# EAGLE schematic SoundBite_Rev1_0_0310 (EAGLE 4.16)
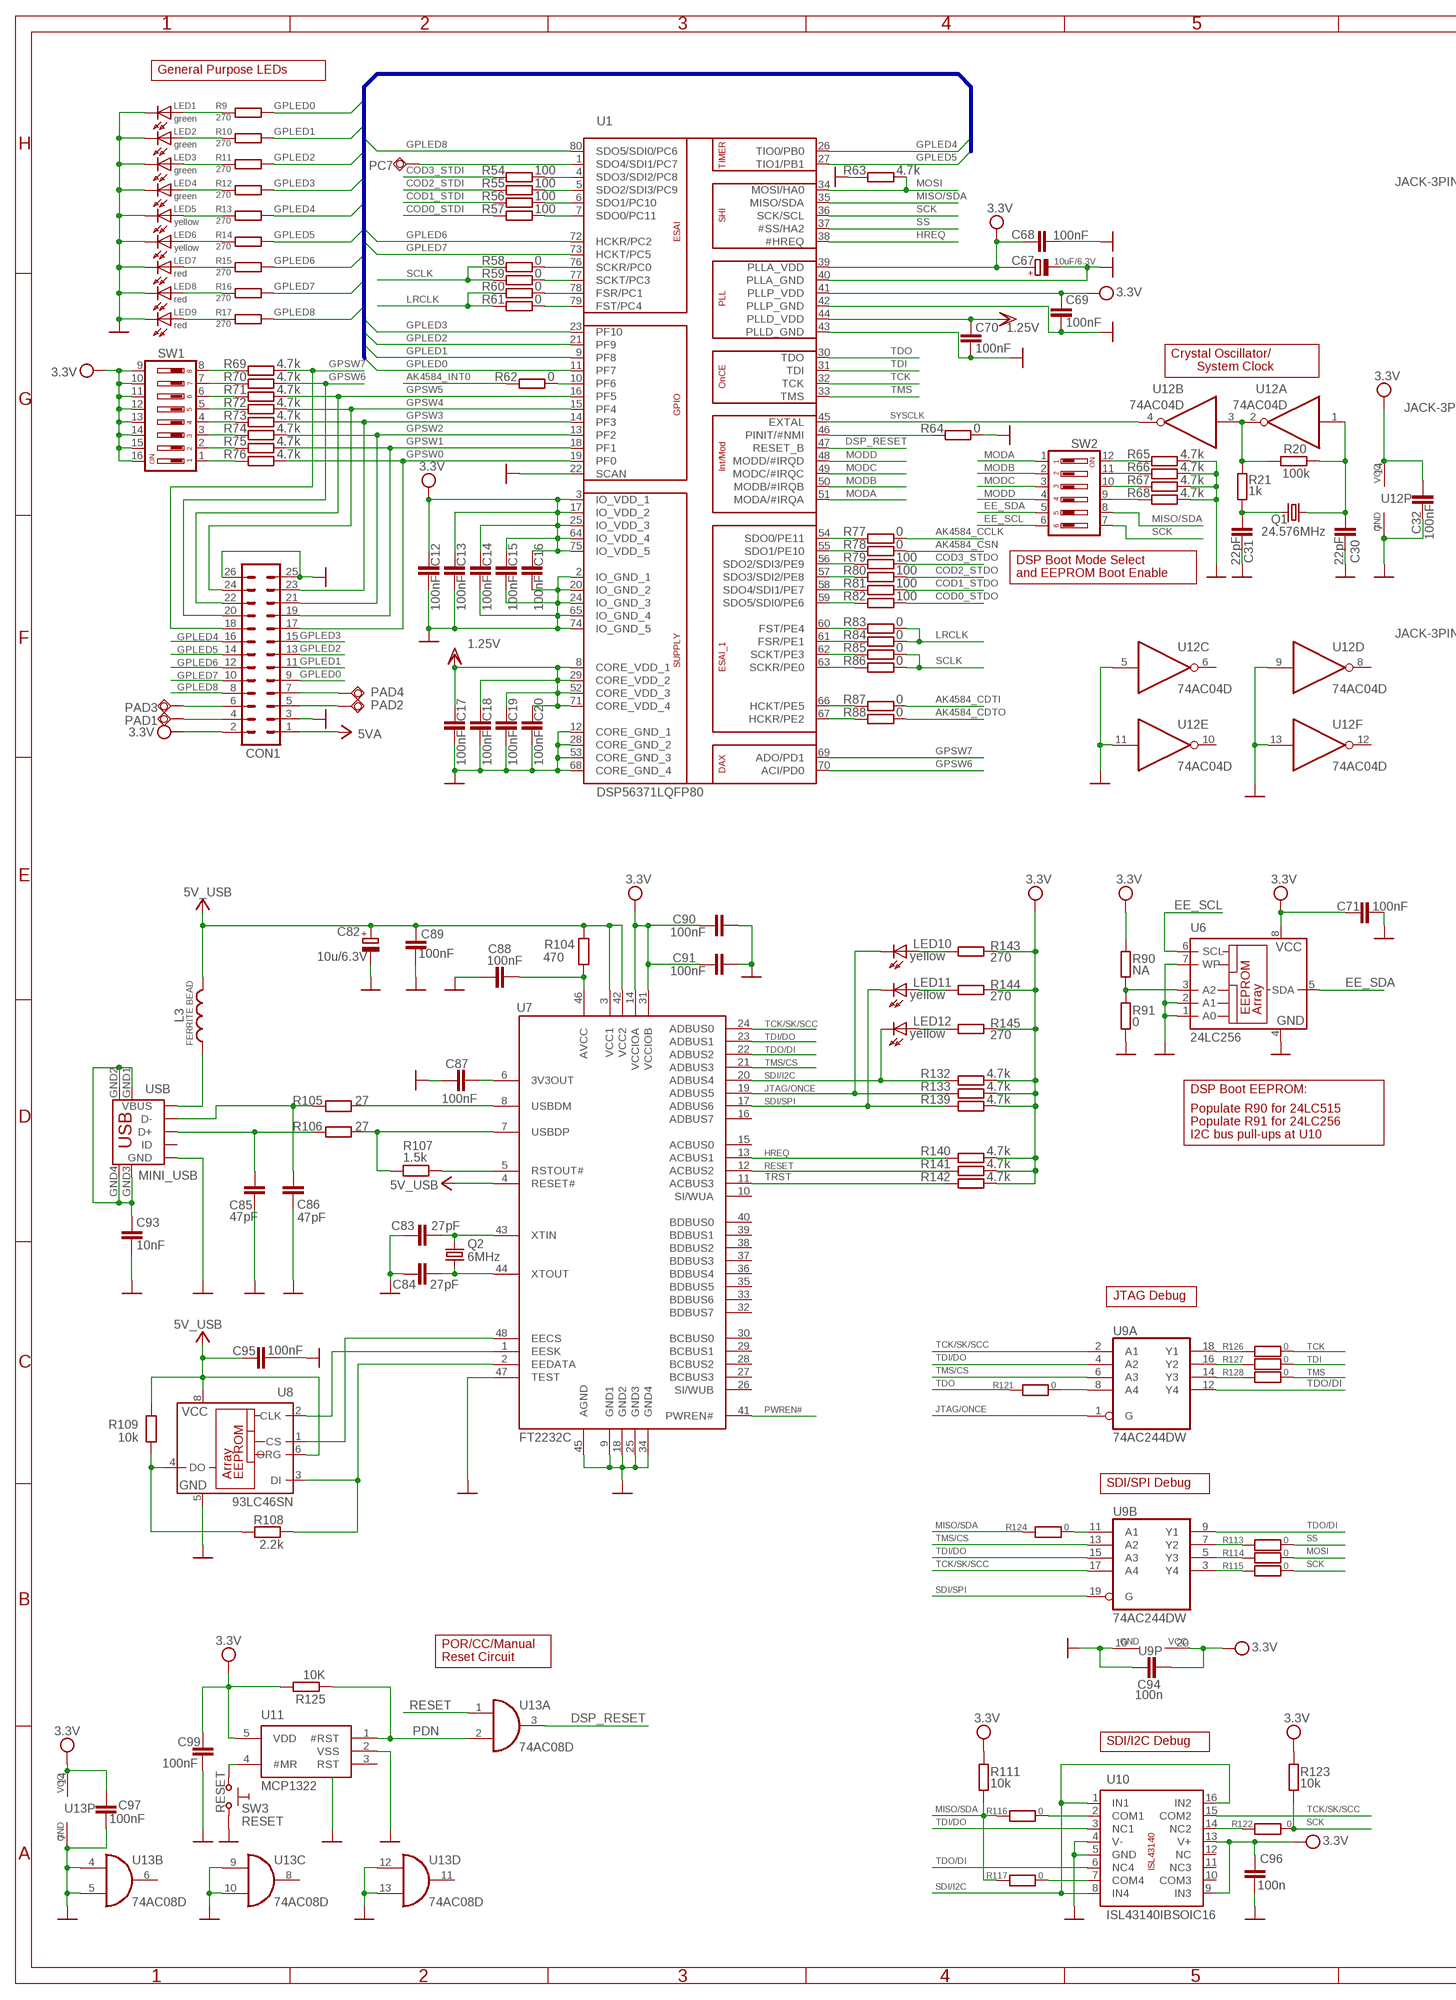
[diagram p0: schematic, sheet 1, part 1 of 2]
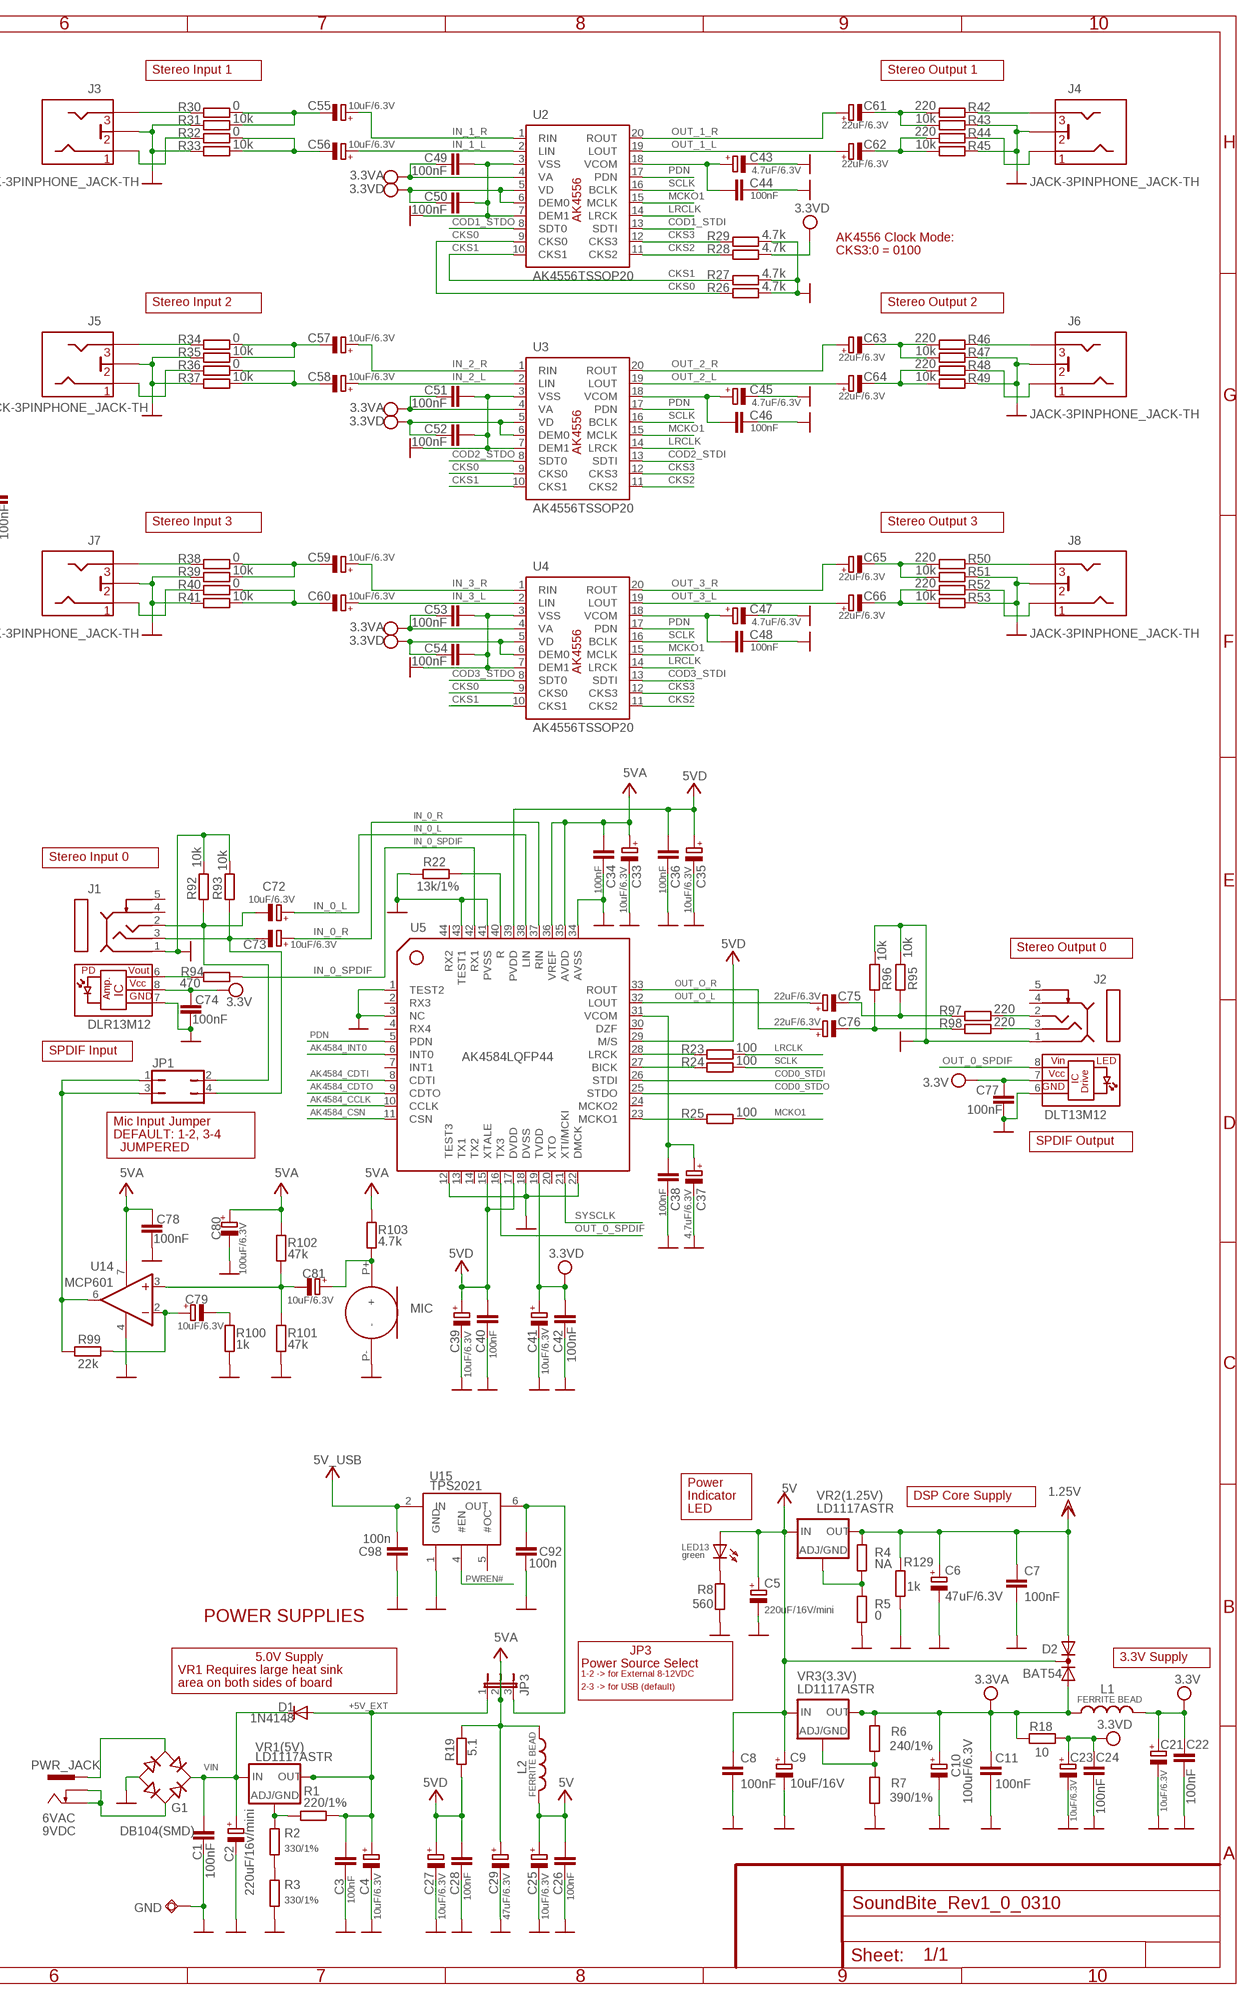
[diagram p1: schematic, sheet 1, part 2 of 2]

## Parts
C1  100nF  C-EUC0805_5MIL  [C0805_5MIL]
C2  220uF/16v/mini  CPOL-EUE3.5-8  [E3,5-8]
C3  100nF  C-EUC0805_5MIL  [C0805_5MIL]
C4  10uF/6.3V  CPOL-EUCT3216  [CT3216]
C5  220uF/16V/mini  CPOL-EUE3.5-8  [E3,5-8]
C6  47uF/6.3V  CPOL-EUCT3528  [CT3528]
C7  100nF  C-EUC0805_5MIL  [C0805_5MIL]
C8  100nF  C-EUC0805_5MIL  [C0805_5MIL]
C9  10uF/16V  CPOL-EUCT3528  [CT3528]
C10  100uF/6.3V  CPOL-EUCT7343  [CT7343]
C11  100nF  C-EUC0805_5MIL  [C0805_5MIL]
C12  100nF  C-EUC0805_5MIL  [C0805_5MIL]
C13  100nF  C-EUC0805_5MIL  [C0805_5MIL]
C14  100nF  C-EUC0805_5MIL  [C0805_5MIL]
C15  100nF  C-EUC0805_5MIL  [C0805_5MIL]
C16  100nF  C-EUC0805_5MIL  [C0805_5MIL]
C17  100nF  C-EUC0805_5MIL  [C0805_5MIL]
C18  100nF  C-EUC0805_5MIL  [C0805_5MIL]
C19  100nF  C-EUC0805_5MIL  [C0805_5MIL]
C20  100nF  C-EUC0805_5MIL  [C0805_5MIL]
C21  10uF/6.3V  CPOL-EUCT3216  [CT3216]
C22  100nF  C-EUC0805_5MIL  [C0805_5MIL]
C23  10uF/6.3V  CPOL-EUCT3216  [CT3216]
C24  100nF  C-EUC0805_5MIL  [C0805_5MIL]
C25  10uF/6.3V  CPOL-EUCT3216  [CT3216]
C26  100nF  C-EUC0805_5MIL  [C0805_5MIL]
C27  10uF/6.3V  CPOL-EUCT3216  [CT3216]
C28  100nF  C-EUC0805_5MIL  [C0805_5MIL]
C29  47uF/6.3V  CPOL-EUCT3528  [CT3528]
C30  22pF  C-EUC0805_5MIL  [C0805_5MIL]
C31  22pF  C-EUC0805_5MIL  [C0805_5MIL]
C32  100nF  C-EUC0805_5MIL  [C0805_5MIL]
C33  10uF/6.3V  CPOL-EUCT3216  [CT3216]
C34  100nF  C-EUC0805_5MIL  [C0805_5MIL]
C35  10uF/6.3V  CPOL-EUCT3216  [CT3216]
C36  100nF  C-EUC0805_5MIL  [C0805_5MIL]
C37  4.7uF/6.3V  CPOL-EUCT3216  [CT3216]
C38  100nF  C-EUC0805_5MIL  [C0805_5MIL]
C39  10uF/6.3V  CPOL-EUCT3216  [CT3216]
C40  100nF  C-EUC0805_5MIL  [C0805_5MIL]
C41  10uF/6.3V  CPOL-EUCT3216  [CT3216]
C42  100nF  C-EUC0805_5MIL  [C0805_5MIL]
C43  4.7uF/6.3V  CPOL-EUCT3216  [CT3216]
C44  100nF  C-EUC0805_5MIL  [C0805_5MIL]
C45  4.7uF/6.3V  CPOL-EUCT3216  [CT3216]
C46  100nF  C-EUC0805_5MIL  [C0805_5MIL]
C47  4.7uF/6.3V  CPOL-EUCT3216  [CT3216]
C48  100nF  C-EUC0805_5MIL  [C0805_5MIL]
C49  100nF  C-EUC0805_5MIL  [C0805_5MIL]
C50  100nF  C-EUC0805_5MIL  [C0805_5MIL]
C51  100nF  C-EUC0805_5MIL  [C0805_5MIL]
C52  100nF  C-EUC0805_5MIL  [C0805_5MIL]
C53  100nF  C-EUC0805_5MIL  [C0805_5MIL]
C54  100nF  C-EUC0805_5MIL  [C0805_5MIL]
C55  10uF/6.3V  CPOL-EUCT3216  [CT3216]
C56  10uF/6.3V  CPOL-EUCT3216  [CT3216]
C57  10uF/6.3V  CPOL-EUCT3216  [CT3216]
C58  10uF/6.3V  CPOL-EUCT3216  [CT3216]
C59  10uF/6.3V  CPOL-EUCT3216  [CT3216]
C60  10uF/6.3V  CPOL-EUCT3216  [CT3216]
C61  22uF/6.3V  CPOL-EUCT3216  [CT3216]
C62  22uF/6.3V  CPOL-EUCT3216  [CT3216]
C63  22uF/6.3V  CPOL-EUCT3216  [CT3216]
C64  22uF/6.3V  CPOL-EUCT3216  [CT3216]
C65  22uF/6.3V  CPOL-EUCT3216  [CT3216]
C66  22uF/6.3V  CPOL-EUCT3216  [CT3216]
C67  10uF/6.3V  CPOL-EUCT3216  [CT3216]
C68  100nF  C-EUC0805_5MIL  [C0805_5MIL]
C69  100nF  C-EUC0805_5MIL  [C0805_5MIL]
C70  100nF  C-EUC0805_5MIL  [C0805_5MIL]
C71  100nF  C-EUC0805_5MIL  [C0805_5MIL]
C72  10uF/6.3V  CPOL-EUCT3216  [CT3216]
C73  10uF/6.3V  CPOL-EUCT3216  [CT3216]
C74  100nF  C-EUC0805_5MIL  [C0805_5MIL]
C75  22uF/6.3V  CPOL-EUCT3216  [CT3216]
C76  22uF/6.3V  CPOL-EUCT3216  [CT3216]
C77  100nF  C-EUC0805_5MIL  [C0805_5MIL]
C78  100nF  C-EUC0805_5MIL  [C0805_5MIL]
C79  10uF/6.3V  CPOL-EUCT3216  [CT3216]
C80  100uF/6.3V  CPOL-EUCT7343  [CT7343]
C81  10uF/6.3V  CPOL-EUCT3216  [CT3216]
C82  10u/6.3V  CPOL-EUCT3216  [CT3216]
C83  27pF  C_0805  [0805]
C84  27pF  C_0805  [0805]
C85  47pF  C_0805  [0805]
C86  47pF  C_0805  [0805]
C87  100nF  C_0805  [0805]
C88  100nF  C_0805  [0805]
C89  100nF  C_0805  [0805]
C90  100nF  C_0805  [0805]
C91  100nF  C_0805  [0805]
C92  100n  C_0805  [0805]
C93  10nF  C-EUC0805_5MIL  [C0805_5MIL]
C94  100n  C_0805  [0805]
C95  100nF  C_0805  [0805]
C96  100n  C_0805  [0805]
C97  100nF  C-EUC0805_5MIL  [C0805_5MIL]
C98  100n  C_0805  [0805]
C99  100nF  C-EUC0805_5MIL  [C0805_5MIL]
CON1  ML26  [ML26]
D1  1N4148  D-SOD-80  [SOD80]
D2  BAT54  DIODE_AC-CA_  [SOT23C]
G1  DB104(SMD)  B-DIL3  [DB104_SMD]
GND  TESTPAD3  [TEST_PAD40/70/SQUARE]
J1  DLR13M12  [GP1FD210RP]
J2  DLT13M12  [GP1FD210RP]
J3  JACK-3PINPHONE_JACK-TH  [PHONE_JACK-TH]
J4  JACK-3PINPHONE_JACK-TH  [PHONE_JACK-TH]
J5  JACK-3PINPHONE_JACK-TH  [PHONE_JACK-TH]
J6  JACK-3PINPHONE_JACK-TH  [PHONE_JACK-TH]
J7  JACK-3PINPHONE_JACK-TH  [PHONE_JACK-TH]
J8  JACK-3PINPHONE_JACK-TH  [PHONE_JACK-TH]
JP1  JP2Q  [JP2Q]
JP3  JP2E  [JP2]
L1  FERRITE BEAD  L-USL0805  [L0805]
L2  FERRITE BEAD  L-USL0805  [L0805]
L3  FERRITE BEAD  L-USL0805  [L0805]
LED1  green  LED_SML-010  [SML-010]
LED2  green  LED_SML-010  [SML-010]
LED3  green  LED_SML-010  [SML-010]
LED4  green  LED_SML-010  [SML-010]
LED5  yellow  LED_SML-010  [SML-010]
LED6  yellow  LED_SML-010  [SML-010]
LED7  red  LED_SML-010  [SML-010]
LED8  red  LED_SML-010  [SML-010]
LED9  red  LED_SML-010  [SML-010]
LED10  yellow  LED_SML-010  [SML-010]
LED11  yellow  LED_SML-010  [SML-010]
LED12  yellow  LED_SML-010  [SML-010]
LED13  green  LED_SML-010  [SML-010]
MIC  MICR  [MIC]
PAD1  TESTPAD80/50  [SMD80/50]
PAD2  TESTPAD80/50  [SMD80/50]
PAD3  TESTPAD80/50  [SMD80/50]
PAD4  TESTPAD80/50  [SMD80/50]
PC7  TESTPAD80/50  [SMD80/50]
PWR_JACK  PWR-JAK3  [PWR_JACK_UNI]
Q1  24.576MHz  HC49/S  [HC49/S]
Q2  6MHz  CRYTALHC49S  [HC49/S@2]
R1  220/1%  R-EU_R0805_5MIL  [R0805_5MIL]
R2  330/1%  R-EU_R0805_5MIL  [R0805_5MIL]
R3  330/1%  R-EU_R0805_5MIL  [R0805_5MIL]
R4  NA  R-EU_R0805_5MIL  [R0805_5MIL]
R5  0  R-EU_R0805_5MIL  [R0805_5MIL]
R6  240/1%  R-EU_R0805_5MIL  [R0805_5MIL]
R7  390/1%  R-EU_R0805_5MIL  [R0805_5MIL]
R8  560  R-EU_R0805_5MIL  [R0805_5MIL]
R9  270  R-EU_R0805_5MIL  [R0805_5MIL]
R10  270  R-EU_R0805_5MIL  [R0805_5MIL]
R11  270  R-EU_R0805_5MIL  [R0805_5MIL]
R12  270  R-EU_R0805_5MIL  [R0805_5MIL]
R13  270  R-EU_R0805_5MIL  [R0805_5MIL]
R14  270  R-EU_R0805_5MIL  [R0805_5MIL]
R15  270  R-EU_R0805_5MIL  [R0805_5MIL]
R16  270  R-EU_R0805_5MIL  [R0805_5MIL]
R17  270  R-EU_R0805_5MIL  [R0805_5MIL]
R18  10  R-EU_R0805_5MIL  [R0805_5MIL]
R19  5.1  R-EU_R0805_5MIL  [R0805_5MIL]
R20  100k  R-EU_R0805_5MIL  [R0805_5MIL]
R21  1k  R-EU_R0805_5MIL  [R0805_5MIL]
R22  13k/1%  R-EU_R0805_5MIL  [R0805_5MIL]
R23  100  R-EU_R0805_5MIL  [R0805_5MIL]
R24  100  R-EU_R0805_5MIL  [R0805_5MIL]
R25  100  R-EU_R0805_5MIL  [R0805_5MIL]
R26  4.7k  R-EU_R0805_5MIL  [R0805_5MIL]
R27  4.7k  R-EU_R0805_5MIL  [R0805_5MIL]
R28  4.7k  R-EU_R0805_5MIL  [R0805_5MIL]
R29  4.7k  R-EU_R0805_5MIL  [R0805_5MIL]
R30  0  R-EU_R0805_5MIL  [R0805_5MIL]
R31  10k  R-EU_R0805_5MIL  [R0805_5MIL]
R32  0  R-EU_R0805_5MIL  [R0805_5MIL]
R33  10k  R-EU_R0805_5MIL  [R0805_5MIL]
R34  0  R-EU_R0805_5MIL  [R0805_5MIL]
R35  10k  R-EU_R0805_5MIL  [R0805_5MIL]
R36  0  R-EU_R0805_5MIL  [R0805_5MIL]
R37  10k  R-EU_R0805_5MIL  [R0805_5MIL]
R38  0  R-EU_R0805_5MIL  [R0805_5MIL]
R39  10k  R-EU_R0805_5MIL  [R0805_5MIL]
R40  0  R-EU_R0805_5MIL  [R0805_5MIL]
R41  10k  R-EU_R0805_5MIL  [R0805_5MIL]
R42  220  R-EU_R0805_5MIL  [R0805_5MIL]
R43  10k  R-EU_R0805_5MIL  [R0805_5MIL]
R44  220  R-EU_R0805_5MIL  [R0805_5MIL]
R45  10k  R-EU_R0805_5MIL  [R0805_5MIL]
R46  220  R-EU_R0805_5MIL  [R0805_5MIL]
R47  10k  R-EU_R0805_5MIL  [R0805_5MIL]
R48  220  R-EU_R0805_5MIL  [R0805_5MIL]
R49  10k  R-EU_R0805_5MIL  [R0805_5MIL]
R50  220  R-EU_R0805_5MIL  [R0805_5MIL]
R51  10k  R-EU_R0805_5MIL  [R0805_5MIL]
R52  220  R-EU_R0805_5MIL  [R0805_5MIL]
R53  10k  R-EU_R0805_5MIL  [R0805_5MIL]
R54  100  R-EU_R0805_5MIL  [R0805_5MIL]
R55  100  R-EU_R0805_5MIL  [R0805_5MIL]
R56  100  R-EU_R0805_5MIL  [R0805_5MIL]
R57  100  R-EU_R0805_5MIL  [R0805_5MIL]
R58  0  R-EU_R0805_5MIL  [R0805_5MIL]
R59  0  R-EU_R0805_5MIL  [R0805_5MIL]
R60  0  R-EU_R0805_5MIL  [R0805_5MIL]
R61  0  R-EU_R0805_5MIL  [R0805_5MIL]
R62  0  R-EU_R0805_5MIL  [R0805_5MIL]
R63  4.7k  R-EU_R0805_5MIL  [R0805_5MIL]
R64  0  R-EU_R0805_5MIL  [R0805_5MIL]
R65  4.7k  R-EU_R0805_5MIL  [R0805_5MIL]
R66  4.7k  R-EU_R0805_5MIL  [R0805_5MIL]
R67  4.7k  R-EU_R0805_5MIL  [R0805_5MIL]
R68  4.7k  R-EU_R0805_5MIL  [R0805_5MIL]
R69  4.7k  R-EU_R0805_5MIL  [R0805_5MIL]
R70  4.7k  R-EU_R0805_5MIL  [R0805_5MIL]
R71  4.7k  R-EU_R0805_5MIL  [R0805_5MIL]
R72  4.7k  R-EU_R0805_5MIL  [R0805_5MIL]
R73  4.7k  R-EU_R0805_5MIL  [R0805_5MIL]
R74  4.7k  R-EU_R0805_5MIL  [R0805_5MIL]
R75  4.7k  R-EU_R0805_5MIL  [R0805_5MIL]
R76  4.7k  R-EU_R0805_5MIL  [R0805_5MIL]
R77  0  R-EU_R0805_5MIL  [R0805_5MIL]
R78  0  R-EU_R0805_5MIL  [R0805_5MIL]
R79  100  R-EU_R0805_5MIL  [R0805_5MIL]
R80  100  R-EU_R0805_5MIL  [R0805_5MIL]
R81  100  R-EU_R0805_5MIL  [R0805_5MIL]
R82  100  R-EU_R0805_5MIL  [R0805_5MIL]
R83  0  R-EU_R0805_5MIL  [R0805_5MIL]
R84  0  R-EU_R0805_5MIL  [R0805_5MIL]
R85  0  R-EU_R0805_5MIL  [R0805_5MIL]
R86  0  R-EU_R0805_5MIL  [R0805_5MIL]
R87  0  R-EU_R0805_5MIL  [R0805_5MIL]
R88  0  R-EU_R0805_5MIL  [R0805_5MIL]
R90  NA  R-EU_R0805_5MIL  [R0805_5MIL]
R91  0  R-EU_R0805_5MIL  [R0805_5MIL]
R92  10k  R-EU_R0805_5MIL  [R0805_5MIL]
R93  10k  R-EU_R0805_5MIL  [R0805_5MIL]
R94  470  R-EU_R0805_5MIL  [R0805_5MIL]
R95  10k  R-EU_R0805_5MIL  [R0805_5MIL]
R96  10k  R-EU_R0805_5MIL  [R0805_5MIL]
R97  220  R-EU_R0805_5MIL  [R0805_5MIL]
R98  220  R-EU_R0805_5MIL  [R0805_5MIL]
R99  22k  R-EU_R0805_5MIL  [R0805_5MIL]
R100  1k  R-EU_R0805_5MIL  [R0805_5MIL]
R101  47k  R-EU_R0805_5MIL  [R0805_5MIL]
R102  47k  R-EU_R0805_5MIL  [R0805_5MIL]
R103  4.7k  R-EU_R0805_5MIL  [R0805_5MIL]
R104  470  R_0805  [0805]
R105  27  R_0805  [0805]
R106  27  R_0805  [0805]
R107  1.5k  R_0805  [0805]
R108  2.2k  R_0805  [0805]
R109  10k  R_0805  [0805]
R111  10k  R-EU_R0805_5MIL  [R0805_5MIL]
R113  0  R_0805  [0805]
R114  0  R_0805  [0805]
R115  0  R_0805  [0805]
R116  0  R_0805  [0805]
R117  0  R_0805  [0805]
R121  0  R_0805  [0805]
R122  0  R_0805  [0805]
R123  10k  R-EU_R0805_5MIL  [R0805_5MIL]
R124  0  R_0805  [0805]
R125  10K  R-EU_R0805_5MIL  [R0805_5MIL]
R126  0  R_0805  [0805]
R127  0  R_0805  [0805]
R128  0  R_0805  [0805]
R129  1k  R-EU_R0805_5MIL  [R0805_5MIL]
R132  4.7k  R-EU_R0805_5MIL  [R0805_5MIL]
R133  4.7k  R-EU_R0805_5MIL  [R0805_5MIL]
R139  4.7k  R-EU_R0805_5MIL  [R0805_5MIL]
R140  4.7k  R-EU_R0805_5MIL  [R0805_5MIL]
R141  4.7k  R-EU_R0805_5MIL  [R0805_5MIL]
R142  4.7k  R-EU_R0805_5MIL  [R0805_5MIL]
R143  270  R-EU_R0805_5MIL  [R0805_5MIL]
R144  270  R-EU_R0805_5MIL  [R0805_5MIL]
R145  270  R-EU_R0805_5MIL  [R0805_5MIL]
SW1  DIP08YL  [DIP08YL]
SW2  DIP06YL  [DIP06YL]
SW3  RESET  SW-TAKT6  [SW-TAKT_6X3.5_SMD]
U1  DSP56371LQFP80  [LQFP80]
U2  AK4556TSSOP20  [TSSOP20]
U3  AK4556TSSOP20  [TSSOP20]
U4  AK4556TSSOP20  [TSSOP20]
U5  AK4584LQFP44  [LQFP44]
U6  24LC256  24LCXX  [SO-08MN]
U7  FT2232C  [FT2232C_LQFP48]
U8  93LC46SN  [SO-08]
U9  74AC244DW  [SO20W]
U10  ISL43140IBSOIC16  [SOIC16]
U11  MCP1322  [SOT23-5]
U12  74AC04D  [SO14]
U13  74AC08D  [SO14]
U14  MCP601  LM307D  [SO08]
U15  TPS2021  TPS2020G8  [R-PDSO-G8]
USB  MINI_USB  MINI_USB9  [USB_MINI_9PIN]
VR1(5V)  LD1117ASTR  LM1117  [SOT223]
VR2(1.25V)  LD1117ASTR  LM1117  [SOT223]
VR3(3.3V)  LD1117ASTR  LM1117  [SOT223]

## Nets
+5V: C5.+ C8.1 C9.+ C25.+ C26.1 D2.3(K) L2.2 LED13.A VR2(1.25V).3(IN) VR3(3.3V).3(IN) ; supply symbol labelled 5V
+5V_EXT: C3.1 C4.+ D1.2(A) JP3.1 R1.2 VR1(5V).2(OUT) VR1(5V).4(RAD)
AK4584_CCLK: R77.2 U5.10(CCLK)
AK4584_CDTI: R87.2 U5.8(CDTI)
AK4584_CDTO: R88.2 U5.9(CDTO)
AK4584_CSN: R78.2 U5.11(CSN)
AK4584_INT0: R62.1 U5.6(INT0)
CKS0: R26.1 U2.9(CKS0) U3.9(CKS0) U4.9(CKS0)
CKS1: R27.1 U2.10(CKS1) U3.10(CKS1) U4.10(CKS1)
CKS2: R28.1 U2.11(CKS2) U3.11(CKS2) U4.11(CKS2)
CKS3: R29.1 U2.12(CKS3) U3.12(CKS3) U4.12(CKS3)
COD0_STDI: R57.1 U5.26(STDI)
COD0_STDO: R82.2 U5.25(STDO)
COD1_STDI: R56.1 U2.13(SDTI)
COD1_STDO: R81.2 U2.8(SDT0)
COD2_STDI: R55.1 U3.13(SDTI)
COD2_STDO: R80.2 U3.8(SDT0)
COD3_STDI: R54.1 U4.13(SDTI)
COD3_STDO: R79.2 U4.8(SDT0)
DSP_RESET: U1.47(RESET_B) U13.3(A:O)
EE_SCL: SW2.6 U6.6(SCL)
EE_SDA: SW2.5 U6.5(SDA)
GND: C1.2 C2.- C3.2 C4.- C5.- C6.- C7.2 C8.2 C9.- C10.- C11.2 C12.2 C13.2 C14.2 C15.2 C16.2 C17.2 C18.2 C19.2 C20.2 C21.- C22.2 C23.- C24.2 C25.- C26.2 C27.- C28.2 C29.- C30.2 C31.2 C32.2 C33.- C34.2 C35.- C36.2 C37.- C38.2 C39.- C40.2 C41.- C42.2 C43.- C44.2 C45.- C46.2 C47.- C48.2 C49.2 C50.2 C51.2 C52.2 C53.2 C54.2 C67.- C68.2 C69.2 C70.2 C71.2 C74.2 C77.2 C78.2 C80.- C82.- C83.P$2 C84.P$2 C85.P$2 C86.P$2 C87.P$2 C88.P$2 C89.P$2 C90.P$1 C91.P$1 C92.P$1 C93.1 C94.P$2 C95.P$1 C96.P$2 C97.2 C98.P$1 C99.2 CON1.3 CON1.25 CON1.26 G1.- GND.P$1(PP) J1.1 J1.7 J2.1 J2.6 J3.2 J4.2 J5.2 J6.2 J7.2 J8.2 LED1.C LED2.C LED3.C LED4.C LED5.C LED6.C LED7.C LED8.C LED9.C MIC.P-(-) R3.1 R5.1 R7.1 R8.1 R22.1 R26.2 R27.2 R29.2 R31.1 R33.1 R35.1 R37.1 R39.1 R41.1 R43.1 R45.1 R47.1 R49.1 R51.1 R53.1 R63.1 R64.2 R65.2 R66.2 R67.2 R68.2 R91.1 R92.2 R93.2 R95.2 R96.2 R100.2 R101.2 R129.1 SW3.P$2 U1.2(IO_GND_1) U1.12(CORE_GND_1) U1.20(IO_GND_2) U1.22(SCAN) U1.24(IO_GND_3) U1.28(CORE_GND_2) U1.40(PLLA_GND) U1.42(PLLP_GND) U1.43(PLLD_GND) U1.53(CORE_GND_3) U1.65(IO_GND_4) U1.68(CORE_GND_4) U1.74(IO_GND_5) U2.3(VSS) U2.7(DEM1) U3.3(VSS) U3.7(DEM1) U4.3(VSS) U4.7(DEM1) U5.1(TEST2) U5.3(NC) U5.12(TEST3) U5.18(DVSS) U5.22(DMCK) U5.34(AVSS) U5.41(PVSS) U5.43(TEST1) U6.1(A0) U6.2(A1) U6.4(GND) U6.7(WP) U7.9(GND1) U7.18(GND2) U7.25(GND3) U7.34(GND4) U7.45(AGND) U7.47(TEST) U8.5(GND) U9.10(P:GND) U10.4(V-) U10.5(GND) U11.2(VSS) U12.5(C:I) U12.7(P:GND) U12.9(D:I) U12.11(E:I) U12.13(F:I) U13.4(B:I0) U13.5(B:I1) U13.7(P:GND) U13.9(C:I0) U13.10(C:I1) U13.12(D:I0) U13.13(D:I1) U14.4(V-) U15.1(GND) USB.GND
GPLED0: CON1.9 R9.2 U1.11(PF7)
GPLED1: CON1.11 R10.2 U1.9(PF8)
GPLED2: CON1.13 R11.2 U1.21(PF9)
GPLED3: CON1.15 R12.2 U1.23(PF10)
GPLED4: CON1.16 R13.2 U1.26(TIO0/PB0)
GPLED5: CON1.14 R14.2 U1.27(TIO1/PB1)
GPLED6: CON1.12 R15.2 U1.72(HCKR/PC2)
GPLED7: CON1.10 R16.2 U1.73(HCKT/PC5)
GPLED8: CON1.8 R17.2 U1.80(SDO5/SDI0/PC6)
GPSW0: CON1.17 R76.2 U1.19(PF0)
GPSW1: CON1.19 R75.2 U1.18(PF1)
GPSW2: CON1.21 R74.2 U1.13(PF2)
GPSW3: CON1.23 R73.2 U1.14(PF3)
GPSW4: CON1.24 R72.2 U1.15(PF4)
GPSW5: CON1.22 R71.2 U1.16(PF5)
GPSW6: CON1.20 R70.2 U1.70(ACI/PD0)
GPSW7: CON1.18 R69.2 U1.69(ADO/PD1)
HREQ: R140.1 U1.38(#HREQ) U7.13(ACBUS1)
IN_0_L: C72.+ U5.38(LIN)
IN_0_R: C73.+ U5.37(RIN)
IN_0_SPDIF: R94.1 U5.42(RX1)
IN_1_L: C56.+ U2.2(LIN)
IN_1_R: C55.+ U2.1(RIN)
IN_2_L: C58.+ U3.2(LIN)
IN_2_R: C57.+ U3.1(RIN)
IN_3_L: C60.+ U4.2(LIN)
IN_3_R: C59.+ U4.1(RIN)
JTAG/ONCE: LED10.C R133.1 U7.19(ADBUS5) U9.1(A:G)
LRCLK: R23.2 R60.1 R61.1 R83.2 R84.2 U2.14(LRCK) U3.14(LRCK) U4.14(LRCK)
MCKO1: R25.2 U2.15(MCLK) U3.15(MCLK) U4.15(MCLK)
MISO/SDA: R111.2 R116.P$2 R117.P$2 R124.P$2 SW2.8 U1.35(MISO/SDA)
MODA: SW2.1 U1.51(MODA/#IRQA)
MODB: SW2.2 U1.50(MODB/#IRQB)
MODC: SW2.3 U1.49(MODC/#IRQC)
MODD: SW2.4 U1.48(MODD/#IRQD)
MOSI: R63.2 R114.P$1 U1.34(MOSI/HA0)
N$1: R22.2 U5.40(R)
N$2: C30.1 Q1.1 R20.1 U12.1(A:I)
N$3: C31.1 Q1.2 R21.1
N$4: R20.2 R21.2 U12.2(A:O) U12.3(B:I)
N$5: C37.+ C38.1 U5.31(VCOM)
N$6: R23.1 U5.28(LRCK)
N$7: R24.1 U5.27(BICK)
N$8: C43.+ C44.1 U2.18(VCOM)
N$9: C45.+ C46.1 U3.18(VCOM)
N$10: C47.+ C48.1 U4.18(VCOM)
N$11: C55.- R30.2 R31.2
N$12: R25.1 U5.23(MCKO1)
N$13: J8.3 R50.1
N$14: R58.2 U1.76(SCKR/PC0)
N$15: LED13.C R8.2
N$16: C56.- R32.2 R33.2
N$17: J3.1 R32.1
N$18: C57.- R34.2 R35.2
N$19: J5.3 R34.1
N$20: C58.- R36.2 R37.2
N$21: J5.1 R36.1
N$22: R59.2 U1.77(SCKT/PC3)
N$23: C59.- R38.2 R39.2
N$24: J7.3 R38.1
N$25: C60.- R40.2 R41.2
N$26: J7.1 R40.1
N$27: R60.2 U1.78(FSR/PC1)
N$28: LED1.A R9.1
N$29: C61.- R42.2 R43.2
N$30: J4.3 R42.1
N$31: C62.- R44.2 R45.2
N$32: J4.1 R44.1
N$33: LED2.A R10.1
N$34: C63.- R46.2 R47.2
N$35: LED3.A R11.1
N$36: R2.1 R3.2
N$37: J6.3 R46.1
N$38: R6.1 R7.2 VR3(3.3V).1(ADJ/GND)
N$39: C64.- R48.2 R49.2
N$40: J6.1 R48.1
N$41: C65.- R50.2 R51.2
N$43: C66.- R52.2 R53.2
N$44: J8.1 R52.1
N$45: R54.2 U1.4(SDO3/SDI2/PC8)
N$46: R55.2 U1.5(SDO2/SDI3/PC9)
N$47: R56.2 U1.6(SDO1/PC10)
N$48: R57.2 U1.7(SDO0/PC11)
N$49: R61.2 U1.79(FST/PC4)
N$50: R62.2 U1.10(PF6)
N$51: R65.1 SW2.12
N$52: R64.1 U1.46(PINIT/#NMI)
N$53: R66.1 SW2.11
N$54: R67.1 SW2.10
N$55: R68.1 SW2.9
N$56: R4.1 R5.2 VR2(1.25V).1(ADJ/GND)
N$57: R69.1 SW1.8
N$58: R70.1 SW1.7
N$59: R71.1 SW1.6
N$60: R72.1 SW1.5
N$61: R73.1 SW1.4
N$62: R74.1 SW1.3
N$63: R75.1 SW1.2
N$64: R76.1 SW1.1
N$65: R77.1 U1.54(SDO0/PE11)
N$66: R78.1 U1.55(SDO1/PE10)
N$67: R79.1 U1.56(SDO2/SDI3/PE9)
N$68: R80.1 U1.57(SDO3/SDI2/PE8)
N$69: R81.1 U1.58(SDO4/SDI1/PE7)
N$70: R82.1 U1.59(SDO5/SDI0/PE6)
N$71: R83.1 U1.60(FST/PE4)
N$72: R84.1 U1.61(FSR/PE1)
N$73: R85.1 U1.62(SCKT/PE3)
N$74: R86.1 U1.63(SCKR/PE0)
N$75: R87.1 U1.66(HCKT/PE5)
N$76: R88.1 U1.67(HCKR/PE2)
N$77: R90.1 R91.2 U6.3(A2)
N$78: C73.- J1.3 JP1.4 R93.1
N$79: C72.- J1.2 JP1.2 R92.1
N$80: J2.2 R97.2
N$81: JP1.1 JP1.3 R99.1 U14.6(OUT)
N$82: C79.+ R99.2 U14.2(-IN)
N$83: J1.6 R94.2
N$84: C79.- R100.1
N$85: C76.- R96.1 R98.1
N$86: C75.- R95.1 R97.1
N$87: J2.3 R98.2
N$88: C81.- R101.1 R102.2 U14.3(+IN)
N$89: C81.+ MIC.P+(+) R103.2
N$90: C87.P$1 U7.6(3V3OUT)
N$91: C86.P$1 R105.P$2 USB.D-
N$92: R105.P$1 U7.8(USBDM)
N$93: R106.P$1 R107.P$1 U7.7(USBDP)
N$94: C84.P$1 Q2.1 U7.44(XTOUT)
N$95: C83.P$1 Q2.2 U7.43(XTIN)
N$96: R108.P$2 R109.P$1 U8.4(DO)
N$97: R108.P$1 U7.2(EEDATA) U8.3(DI)
N$98: U7.48(EECS) U8.1(CS)
N$99: U7.1(EESK) U8.2(CLK)
N$100: C88.P$1 R104.P$1 U7.46(AVCC)
N$101: L3.1 USB.VBUS
N$102: C92.P$2 JP3.3 U15.6(OUT) U15.7(OUT1) U15.8(OUT2)
N$103: C85.P$1 R106.P$2 USB.D+
N$104: G1.AC1 PWR_JACK.- PWR_JACK.--
N$105: G1.AC2 PWR_JACK.+
N$106: R107.P$2 U7.5(RSTOUT#)
N$107: R126.P$2 U9.18(A:Y1)
N$108: R127.P$2 U9.16(A:Y2)
N$109 [pwr]: C93.2 USB.GND1 USB.GND2 USB.GND3 USB.GND4
N$110: SW3.P$1 U11.4(#MR)
N$111: R128.P$2 U9.14(A:Y3)
N$112: R113.P$2 U9.7(B:Y2)
N$113: PC7.P$1(PP) U1.1(SDO4/SDI1/PC7)
N$114: R114.P$2 U9.5(B:Y3)
N$115: R115.P$2 U9.3(B:Y4)
N$116: R121.P$1 U9.8(A:A4)
N$117: LED4.A R12.1
N$118: LED5.A R13.1
N$119: LED6.A R14.1
N$120: R124.P$1 U9.11(B:A1)
N$121: R116.P$1 U10.2(COM1)
N$122: R117.P$1 U10.7(COM4)
N$123: R122.P$2 U10.14(NC2)
N$124: LED7.A R15.1
N$125: LED8.A R16.1
N$126: LED9.A R17.1
N$127: LED10.A R143.1
N$128: LED11.A R144.1
N$129: CON1.6 PAD3.P$1(PP)
N$130: LED12.A R145.1
N$131: CON1.4 PAD1.P$1(PP)
N$132: CON1.7 PAD4.P$1(PP)
N$133: CON1.5 PAD2.P$1(PP)
N$134: J3.3 R30.1
N$727: R1.1 R2.2 VR1(5V).1(ADJ/GND)
OUT_0_SPDIF: J2.8 U5.16(TX3)
OUT_1_L: C62.+ U2.19(LOUT)
OUT_1_R: C61.+ U2.20(ROUT)
OUT_2_L: C64.+ U3.19(LOUT)
OUT_2_R: C63.+ U3.20(ROUT)
OUT_3_L: C66.+ U4.19(LOUT)
OUT_3_R: C65.+ U4.20(ROUT)
OUT_O_L: C75.+ U5.32(LOUT)
OUT_O_R: C76.+ U5.33(ROUT)
PDN: R125.1 U2.17(PDN) U3.17(PDN) U4.17(PDN) U5.5(PDN) U11.1(#RST) U13.2(A:I1)
PWREN#: U7.41(PWREN#) U15.4(#EN)
RESET: R141.1 U7.12(ACBUS2) U13.1(A:I0)
SCK: R115.P$1 R122.P$1 R123.2 SW2.7 U1.36(SCK/SCL)
SCLK: R24.2 R58.1 R59.1 R85.2 R86.2 U2.16(BCLK) U3.16(BCLK) U4.16(BCLK)
SDI/I2C: LED12.C R132.1 U7.20(ADBUS4) U10.1(IN1) U10.8(IN4) U10.16(IN2)
SDI/SPI: LED11.C R139.1 U7.17(ADBUS6) U9.19(B:G)
SS: R113.P$1 U1.37(#SS/HA2)
SYSCLK: U1.45(EXTAL) U5.21(XTI/MCKI) U12.4(B:O)
TCK: R126.P$1 U1.32(TCK)
TCK/SK/SCC: U7.24(ADBUS0) U9.2(A:A1) U9.17(B:A4) U10.15(COM2)
TDI: R127.P$1 U1.31(TDI)
TDI/DO: U7.23(ADBUS1) U9.4(A:A2) U9.15(B:A3) U10.3(NC1)
TDO: R121.P$2 U1.30(TDO)
TDO/DI: U7.22(ADBUS2) U9.9(B:Y1) U9.12(A:Y4) U10.6(NC4)
TMS: R128.P$1 U1.33(TMS)
TMS/CS: U7.21(ADBUS3) U9.6(A:A3) U9.13(B:A2)
TRST: R142.1 U7.11(ACBUS3)
V+: C29.+ C33.+ C34.1 C78.1 C80.+ CON1.1 JP3.2 L2.1 R19.2 R102.1 R103.1 U5.35(AVDD) U5.36(VREF) U14.7(V+) ; supply symbol labelled 5VA
VCC: C12.1 C13.1 C14.1 C15.1 C16.1 C21.+ C22.1 C32.1 C67.+ C68.1 C69.1 C71.1 C74.1 C77.1 C90.P$2 C91.P$2 C94.P$1 C96.P$1 C97.1 C99.1 CON1.2 J1.8 J2.7 L1.2 R90.2 R111.1 R123.1 R125.2 R132.2 R133.2 R139.2 R140.2 R141.2 R142.2 R143.2 R144.2 R145.2 SW1.9 SW1.10 SW1.11 SW1.12 SW1.13 SW1.14 SW1.15 SW1.16 U1.3(IO_VDD_1) U1.17(IO_VDD_2) U1.25(IO_VDD_3) U1.39(PLLA_VDD) U1.41(PLLP_VDD) U1.64(IO_VDD_4) U1.75(IO_VDD_5) U6.8(VCC) U7.14(VCCIOA) U7.31(VCCIOB) U9.20(P:VCC) U10.9(IN3) U10.13(V+) U11.5(VDD) U12.14(P:VCC) U13.14(P:VCC) ; supply symbol labelled 3.3V
VCCINT: C82.+ C89.P$1 C95.P$2 C98.P$2 L3.2 R104.P$2 R109.P$2 U7.3(VCC1) U7.4(RESET#) U7.42(VCC2) U8.6(ORG) U8.8(VCC) U15.2(IN) U15.3(IN1) ; supply symbol labelled 5V_USB
VCCIO: C27.+ C28.1 C35.+ C36.1 C39.+ C40.1 R19.1 U5.15(XTALE) U5.17(DVDD) U5.29(M/S) U5.39(PVDD) ; supply symbol labelled 5VD
VDD: C6.+ C7.1 C17.1 C18.1 C19.1 C20.1 C70.1 D2.2(A2) R4.2 R129.2 U1.8(CORE_VDD_1) U1.29(CORE_VDD_2) U1.44(PLLD_VDD) U1.52(CORE_VDD_3) U1.71(CORE_VDD_4) VR2(1.25V).2(OUT) VR2(1.25V).4(RAD) ; supply symbol labelled 1.25V
VEE: C10.+ C11.1 C49.1 C51.1 C53.1 D2.1(A1) L1.1 R6.2 R18.2 U2.4(VA) U3.4(VA) U4.4(VA) VR3(3.3V).2(OUT) VR3(3.3V).4(RAD) ; supply symbol labelled 3.3VA
VIN: C1.1 C2.+ D1.1(C) G1.+ VR1(5V).3(IN)
VPP: C23.+ C24.1 C41.+ C42.1 C50.1 C52.1 C54.1 R18.1 R28.2 U2.5(VD) U2.6(DEM0) U3.5(VD) U3.6(DEM0) U4.5(VD) U4.6(DEM0) U5.19(TVDD) ; supply symbol labelled 3.3VD
Unconnected: J1.4 J1.5 J2.4 J2.5 U5.2(RX3) U5.4(RX4) U5.7(INT1) U5.13(TX1) U5.14(TX2) U5.20(XTO) U5.24(MCKO2) U5.30(DZF) U5.44(RX2) U7.10(SI/WUA) U7.15(ACBUS0) U7.16(ADBUS7) U7.26(SI/WUB) U7.27(BCBUS3) U7.28(BCBUS2) U7.29(BCBUS1) U7.30(BCBUS0) U7.32(BDBUS7) U7.33(BDBUS6) U7.35(BDBUS5) U7.36(BDBUS4) U7.37(BDBUS3) U7.38(BDBUS2) U7.39(BDBUS1) U7.40(BDBUS0) U8.7(NU) U10.10(COM3) U10.11(NC3) U10.12(NC) U11.3(RST) U12.6(C:O) U12.8(D:O) U12.10(E:O) U12.12(F:O) U13.6(B:O) U13.8(C:O) U13.11(D:O) U15.5(#OC) USB.ID

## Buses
GPLED[0..8]

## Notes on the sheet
- General Purpose LEDs | Stereo Input 1 | Stereo Output 1
- AK4556 Clock Mode:
- CKS3:0 = 0100
- Stereo Input 2 | Stereo Output 2
- Crystal Oscillator/
- System Clock
- Stereo Input 3 | Stereo Output 3
- DSP Boot Mode Select
- and EEPROM Boot Enable
- Stereo Input 0
- Stereo Output 0
- SPDIF Input
- DSP Boot EEPROM:
- Populate R90 for 24LC515
- Populate R91 for 24LC256 | Mic Input Jumper
- I2C bus pull-ups at U10 | DEFAULT: 1-2, 3-4
- SPDIF Output
- JUMPERED
- JTAG Debug
- SDI/SPI Debug | Power
- Indicator | DSP Core Supply
- LED
- POWER SUPPLIES
- POR/CC/Manual
- JP3
- Reset Circuit | 5.0V Supply | 3.3V Supply
- Power Source Select
- VR1 Requires large heat sink
- 1-2 -> for External 8-12VDC
- area on both sides of board
- 2-3 -> for USB (default)
- SDI/I2C Debug
- RESET | 6VAC
- 9VDC

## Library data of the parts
C1 C3 C7 C8 C11-C20 C22 C24 C26 C28 C30-C32 C34 C36 C38 C40 C42 C44 C46 C48-C54 C68-C71 C74 C77 C78 C93 C97 C99 = rcl:C-EU: CAPACITOR, European symbol
C2 C4-C6 C9 C10 C21 C23 C25 C27 C29 C33 C35 C37 C39 C41 C43 C45 C47 C55-C67 C72 C73 C75 C76 C79-C82 = rcl:CPOL-EU: POLARIZED CAPACITOR, European symbol
C83-C92 C94-C96 C98 = 1:C_?
CON1 = con-harting-ml:ML26: HARTING
D1 = semicon-smd-ipc:D-: DIODE
D2 = semicon-smd-ipc:DIODE_AC-CA_: DUAL DIODE
G1 = DOUBLE-SIDE:B-DIL: RECTIFIER
GND PAD1-PAD4 PC7 = gogo:TESTPAD: drill 40mils, diameter 70mils
J1 = OLIMEX_CONNECTORS:DLR13M1: DATA LINK: DLR13M1 Light Receiving Unit Absolute Maximum Ratings( Ta = 25C): Supply Voltage(Vcc): 6 V; Storage Temperature(Tstg): -30 to 80C Operating Temperature(Topr): -20 to 70C Soldering Temperature Tsol 260C, Soldering time lower than 5s / 2times.
J2 = OLIMEX_CONNECTORS:DLT13M1: DATA LINK: DLT13M1 Light Transmitting Unit Absolute Maximum Ratings( Ta = 25)C: Supply Voltage(Vcc) : -0.5 to 7 V ; DC Input Voltage (Vin): -0.5 to Vcc+0.5 V; Power Dissipation(P): 120mW; Storage Temperature(Tstg): -30 to 80 C; Operating Temperature(Topr): -20 to 70 C; Soldering Temperature(Tsol):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
J3-J8 = gogo:JACK-3PIN
JP1 = jumper:JP2Q: JUMPER
JP3 = jumper:JP2E: JUMPER
L1-L3 = rcl:L-US: INDUCTOR, American symbol
LED1-LED13 = 877_enc_dec:LED_SML-010
MIC = DOUBLE-SIDE:MIC: ELECTRETE MICROPHONE
PWR_JACK = gogo:PWR-JAK
Q1 = crystal:HC49/S: CRYSTAL
Q2 = crystal:CRYTAL: CRYSTAL
R1-R88 R90-R103 R111 R123 R125 R129 R132 R133 R139-R145 = rcl:R-EU_: RESISTOR, European symbol
R104-R109 R113-R117 R121 R122 R124 R126-R128 = 1:R_?
SW1 = switch-dil:DIP08YL: DIL/CODE SWITCH
SW2 = switch-dil:DIP06YL: DIL/CODE SWITCH
SW3 = gogo:SW-TAKT
U1 = OLIMEX_IC:DSP56371
U2-U4 = OLIMEX_IC:AK4556: AK4556 3V, 192kHz, 24Bit CODEC Power supply: 2.4 - 3.6V; Power Supply Current: 27.5mA; Operating temperature: from -40 to +85 degree;
U5 = OLIMEX_IC:AK4584
U6 = gogo:24LCXX
U7 = OLIMEX_IC:FT2232C
U8 = microchip:93*: Serial EPROM 1 K/2 K/4 K, low voltage, Microwire
U9 = 74xx-eu:74*244: Octal BUFFER and LINE DRIVER, 3-state
U10 = OLIMEX_IC:ISL43140IB: ISL43140 Low-Voltage, Single and Dual Supply, High Performance, Quad SPST, Analog Switches
U11 = OLIMEX_IC:MCP1322: Voltage Supervisor MCP1319/19M/22 Features  Low supply current: 1 ?A (typ.), 10 ?A (max.)  Precision monitoring trip point options: - 2.9V and 4.6V (Standard Offerings) - 2.0V to 4.7V in 100 mV increments, (Contact the local Microchip Sales Office)  Resets microcontroller in a power-loss event 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
U12 = 74xx-eu:74*04: Hex INVERTER
U13 = 74xx-eu:74*08: Quad 2-input AND gate
U14 = linear:LM307: OP AMP
U15 = OLIMEX_IC:TPS2020: TPS2020,21,22,23,24
USB = OLIMEX_CONNECTORS:MINI_USB9
VR1(5V) VR2(1.25V) VR3(3.3V) = arm:LM1117

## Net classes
0 default: width 0.076 mm
1 pwr: width 0.254 mm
